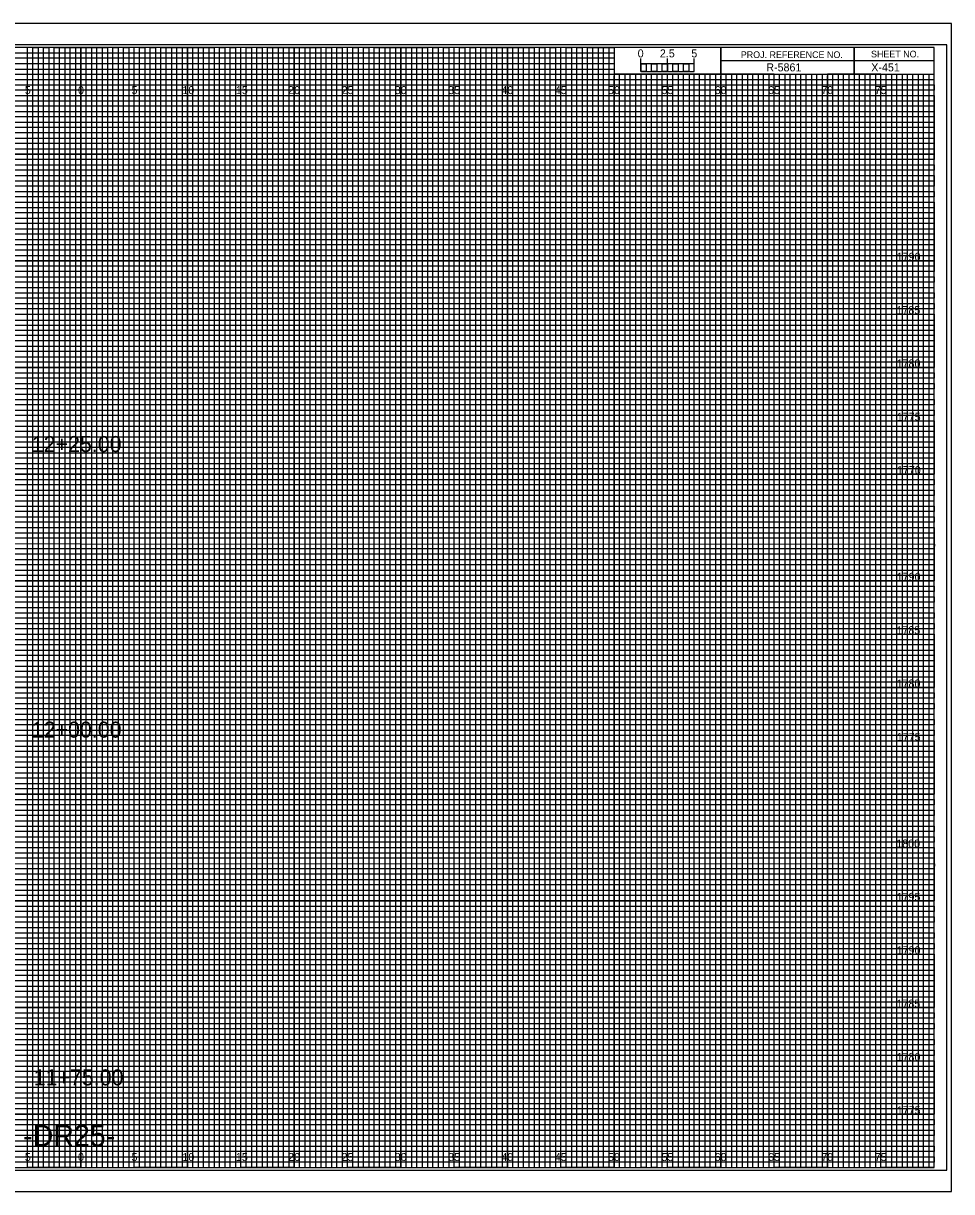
# Model space of a CAD drawing. Extents: x -7 to 162, y -2 to 327.
# Drawn here: x 74.6 to 161.7, y 217.7 to 327.2 of the extents above; entities that cross this region are included whole.
import ezdxf

# ---------------------------------------------------------------- set-up
doc = ezdxf.new("R2010")
doc.units = 0
for name, color, linetype in [('Prop Horizontal Alignment', 7, 'Continuous'), ('Prop XS Alignment Label', 7, 'Continuous'), ('Prop XS Bar Scale Labels', 7, 'Continuous'), ('Prop XS Project Number', 7, 'Continuous'), ('Prop XS Sheet Number', 7, 'Continuous'), ('Raster_Level_0', 7, 'Continuous'), ('Scratch_Level_3', 7, 'Continuous'), ('Sheet Cross Section CELL', 7, 'Continuous'), ('Sheet Cross Section Grid Major CELL', 7, 'Continuous'), ('Sheet Cross Section Grid Middle CELL', 7, 'Continuous'), ('Sheet Cross Section Grid Minor 1 CELL', 7, 'Continuous'), ('Sheet Cross Section Grid Minor 2 CELL', 7, 'Continuous'), ('Sheet Cross Section Scale CELL', 7, 'Continuous'), ('Sheet Cutting Line CELL', 7, 'Continuous'), ('Sheet DOT Grid CELL', 7, 'Continuous'), ('Sheet Plot Border Inside CELL', 7, 'Continuous'), ('Sheet Plot Border Outside CELL', 7, 'Continuous')]:
    doc.layers.add(name, color=color, linetype=linetype)

msp = doc.modelspace()

# ---------------------------------------------------------------- linework, layer by layer
at = {"layer": 'Sheet Cross Section CELL'}
for p, q in [((152.5, 325), (152.5, 322.5)), ((152.5, 322.5), (152.5, 325)), ((160, 323.75), (140, 323.75)), ((140, 323.75), (140, 322.5)), ((140, 322.5), (160, 322.5))]:
    msp.add_line(p, q, dxfattribs=at)
for points in [[(160, 325), (0, 325), (0, 220), (160, 220)], [(140, 325), (130, 325), (130, 322.51), (140, 322.51)], [(160, 325), (140, 325), (140, 322.5), (160, 322.5)]]:
    msp.add_lwpolyline(points, close=True, dxfattribs=at)
at = {"layer": 'Sheet Cross Section Grid Major CELL'}
for p, q in [((75, 325), (70, 325)), ((75, 220), (75, 325)), ((85, 325), (80, 325)), ((80, 325), (80, 220)), ((85, 220), (85, 325)), ((95, 325), (90, 325)), ((90, 325), (90, 220)), ((95, 220), (95, 325)), ((105, 325), (100, 325)), ((100, 325), (100, 220)), ((105, 220), (105, 325)), ((115, 325), (110, 325)), ((110, 325), (110, 220)), ((115, 220), (115, 325)), ((125, 325), (120, 325)), ((120, 325), (120, 220)), ((125, 220), (125, 325)), ((130, 325), (130, 220)), ((135, 220), (135, 322.5)), ((145, 322.5), (140, 322.5)), ((140, 322.5), (140, 220)), ((145, 220), (145, 322.5)), ((155, 322.5), (150, 322.5)), ((150, 322.5), (150, 220)), ((155, 220), (155, 322.5)), ((80, 220), (75, 220)), ((90, 220), (85, 220)), ((100, 220), (95, 220)), ((110, 220), (105, 220)), ((120, 220), (115, 220)), ((130, 220), (125, 220)), ((140, 220), (135, 220)), ((150, 220), (145, 220)), ((160, 220), (155, 220)), ((160, 220), (160, 220))]:
    msp.add_line(p, q, dxfattribs=at)
for points in [[(0, 320), (160, 320), (160, 315), (0, 315)], [(0, 310), (160, 310), (160, 305), (0, 305)], [(0, 300), (160, 300), (160, 295), (0, 295)], [(0, 290), (160, 290), (160, 285), (0, 285)], [(0, 280), (160, 280), (160, 275), (0, 275)], [(0, 270), (160, 270), (160, 265), (0, 265)], [(0, 260), (160, 260), (160, 255), (0, 255)], [(0, 250), (160, 250), (160, 245), (0, 245)], [(0, 240), (160, 240), (160, 235), (0, 235)], [(0, 230), (160, 230), (160, 225), (0, 225)]]:
    msp.add_lwpolyline(points, dxfattribs=at)
at = {"layer": 'Sheet Cross Section Grid Middle CELL'}
for points in [[(72.5, 220), (77.5, 220), (77.5, 325), (82.5, 325), (82.5, 220), (87.5, 220), (87.5, 325), (92.5, 325), (92.5, 220), (97.5, 220), (97.5, 325), (102.5, 325), (102.5, 220), (107.5, 220), (107.5, 325), (112.5, 325), (112.5, 220), (117.5, 220), (117.5, 325), (122.5, 325), (122.5, 220), (127.5, 220), (127.5, 325), (129.97, 325), (130, 325), (130, 322.5), (132.5, 322.5), (132.5, 220), (137.5, 220), (137.5, 322.5), (142.5, 322.5), (142.5, 220), (147.5, 220), (147.5, 322.5), (152.5, 322.5), (152.5, 220), (157.5, 220), (157.5, 322.5)], [(0, 322.5), (137.5, 322.5)], [(0, 312.5), (160, 312.5), (160, 317.5), (0, 317.5)], [(0, 302.5), (160, 302.5), (160, 307.5), (0, 307.5)], [(0, 292.5), (160, 292.5), (160, 297.5), (0, 297.5)], [(0, 282.5), (160, 282.5), (160, 287.5), (0, 287.5)], [(0, 272.5), (160, 272.5), (160, 277.5), (0, 277.5)], [(0, 262.5), (160, 262.5), (160, 267.5), (0, 267.5)], [(0, 252.5), (160, 252.5), (160, 257.5), (0, 257.5)], [(0, 242.5), (160, 242.5), (160, 247.5), (0, 247.5)], [(0, 232.5), (160, 232.5), (160, 237.5), (0, 237.5)], [(0, 222.5), (160, 222.5), (160, 227.5), (0, 227.5)]]:
    msp.add_lwpolyline(points, dxfattribs=at)
at = {"layer": 'Sheet Cross Section Grid Minor 1 CELL'}
for p, q in [((0, 324.5), (130, 324.5)), ((130, 324.5), (130, 323.99)), ((130, 323.99), (0, 323.99)), ((0, 323.5), (130, 323.5)), ((130, 323.5), (130, 322.94)), ((130, 322.94), (0, 322.94)), ((0, 322), (160, 322))]:
    msp.add_line(p, q, dxfattribs=at)
for points in [[(0, 321.5), (135, 321.5), (160, 321.5), (160, 321), (0, 321)], [(0, 320.5), (160, 320.5), (160, 319.5), (0, 319.5)], [(0, 319), (160, 319), (160, 318.5), (0, 318.49)], [(0, 318), (160, 318), (160, 317), (0, 317)], [(0, 316.5), (160, 316.5), (160, 316), (0, 316)], [(0, 315.5), (160, 315.5), (160, 314.5), (0, 314.5)], [(0, 314), (160, 314), (160, 313.5), (0, 313.5)], [(0, 313), (160, 313), (160, 312), (0, 312)], [(0, 311.5), (160, 311.5), (160, 311), (0, 311)], [(0, 310.5), (160, 310.5), (160, 309.5), (0, 309.5)], [(0, 309), (160, 309), (160, 308.5), (0, 308.5)], [(0, 308), (160, 308), (160, 306.98), (160, 306.5), (160, 306), (0, 306)], [(0, 307), (160, 307), (160, 306.5), (0, 306.5)], [(0, 305.5), (160, 305.5), (160, 304.5), (0, 304.51)], [(0, 304.51), (160, 304.5), (160, 304), (0, 304)], [(0, 303.5), (160, 303.5), (160, 303), (0, 303)], [(0, 302), (160, 302), (160, 301.5), (0, 301.5)], [(0, 301), (160, 301), (160, 300.5), (0, 300.5)], [(-0.04, 299.44), (160, 299.44), (160, 298.94), (-0.04, 298.94)], [(0, 298.5), (160, 298.5), (160, 298), (0, 298)], [(0, 297), (160, 297), (160, 296.5), (0, 296.5)], [(0, 296), (160, 296), (160, 295.5), (0, 295.5)], [(0, 294.5), (160, 294.5), (160, 294), (0, 294)], [(0, 293.5), (160, 293.5), (160, 293), (0, 293)], [(0, 292), (160, 292), (160, 291.5), (0, 291.5)], [(0, 291), (160, 291), (160, 290.5), (0, 290.5)], [(0, 289.5), (160, 289.5), (160, 288.99), (0, 289)], [(0, 288.5), (160, 288.5), (160, 288), (0, 288)], [(0, 287), (160, 287), (160, 286.5), (0, 286.5)], [(0, 286), (160, 286), (160, 285.5), (0, 285.5)], [(0, 284.5), (160, 284.5), (160, 284), (0, 284)], [(0, 283.5), (160, 283.5), (160, 283), (0, 283)], [(0, 282), (160, 282), (160, 281.5), (0, 281.5)], [(0, 281), (160, 281), (160, 280.5), (0, 280.5)], [(0, 279.5), (160, 279.5), (160, 279), (0, 279)], [(0, 278.5), (160.03, 278.45), (160, 278), (0, 278)], [(0, 277), (160, 277), (160, 276.5), (0, 276.5)], [(0, 276), (160, 276), (160, 275.5), (0, 275.5)], [(0, 274.5), (160, 274.5), (160, 274), (0, 274)], [(0, 273.5), (160, 273.5), (160, 273), (0, 273)], [(0, 272), (160, 272), (160, 271.5), (0, 271.5)], [(0, 271), (160, 271), (160, 270.5), (0, 270.5)], [(0, 269.5), (160, 269.5), (160, 269), (0, 269)], [(0, 268.5), (160, 268.5), (160, 268), (0, 268)], [(0, 267), (160, 267), (160, 266.5), (0, 266.5)], [(0, 266), (160, 266), (160, 265.5), (0, 265.5)], [(0, 264.5), (160, 264.5), (160, 264), (0, 264)], [(0, 263.5), (160, 263.5), (160, 263), (0, 263)], [(0, 262), (160, 262), (160, 261.5), (0, 261.5)], [(0, 261), (160, 261), (160, 260.5), (0, 260.5)], [(0, 259.5), (160, 259.5), (160, 258.99), (0, 259)], [(0, 258.5), (160, 258.5), (160, 258), (0, 258)], [(0, 257), (160, 257), (160, 256.5), (0, 256.5)], [(0, 256), (160, 256), (160, 255.5), (0, 255.5)], [(0, 254.5), (160, 254.5), (160, 254), (0, 254)], [(0, 253.5), (160, 253.5), (160, 253), (0, 253)], [(0, 252), (160, 252), (160, 251.5), (0, 251.5)], [(0, 251), (160, 251), (160, 250.5), (0, 250.5)], [(0, 249.5), (160, 249.5), (160, 249), (0, 249)], [(0, 248.5), (160.03, 248.46), (160, 248), (0, 248)], [(0, 247), (160, 247), (160, 246.5), (0, 246.5)], [(0, 246), (160, 246), (160, 245.5), (0, 245.5)], [(0, 244.5), (160, 244.5), (160, 244), (0, 244)], [(0, 243.5), (160, 243.5), (160, 243), (0, 243)], [(0, 242), (160, 242), (160, 241.5), (0, 241.5)], [(0, 241), (160, 241), (160, 240.5), (0, 240.5)], [(0, 239.5), (160, 239.5), (160, 239), (0, 239)], [(0, 238.5), (160, 238.5), (160, 238), (0, 238)], [(0, 237), (160, 237), (160, 236.5), (0, 236.5)], [(0, 236), (160, 236), (160, 235.5), (0, 235.5)], [(0, 234.5), (160, 234.5), (160, 234), (0, 234)], [(0, 233.5), (160, 233.5), (160, 233), (0, 233)], [(0, 232), (160, 232), (160, 231.5), (0, 231.5)], [(0, 231), (160, 231), (160, 230.5), (0, 230.5)], [(0, 229.5), (160, 229.5), (160, 229), (0, 229)], [(0, 228.5), (160, 228.5), (160, 228), (0, 228)], [(0, 227), (160, 227), (160, 226.5), (0, 226.5)], [(0, 226), (160, 226), (160, 225.5), (0, 225.5)], [(0, 224.5), (160, 224.5), (160, 224), (0, 224)], [(0, 223.5), (160, 223.5), (160, 223), (0, 223)], [(0, 222), (160, 222), (160, 221.5), (0, 221.5)], [(0, 221), (160, 221), (160, 220.5), (0, 220.5)]]:
    msp.add_lwpolyline(points, dxfattribs=at)
at = {"layer": 'Sheet Cross Section Grid Minor 2 CELL'}
for p, q in [((133.5, 322.5), (133, 322.5)), ((133, 322.5), (133, 220)), ((133.5, 220), (133.5, 322.5)), ((134.5, 322.5), (134, 322.5)), ((134, 322.5), (134, 220)), ((134.5, 220), (134.5, 322.5)), ((133, 220), (132.5, 220)), ((134, 220), (133.5, 220))]:
    msp.add_line(p, q, dxfattribs=at)
for points in [[(75, 220), (75.5, 220), (75.5, 325), (76, 325), (76, 220)], [(76, 220), (76.5, 220), (76.5, 325), (77, 325), (77, 220)], [(77.5, 220), (78, 220), (78, 325), (78.5, 325), (78.5, 220)], [(78.5, 220), (79, 220), (79, 325), (79.5, 325), (79.5, 220)], [(80, 220), (80.5, 220), (80.5, 325), (81, 325), (81, 220)], [(81, 220), (81.5, 220), (81.5, 325), (82, 325), (82, 220)], [(82.5, 220), (83, 220), (83, 325), (83.5, 325), (83.5, 220)], [(83.5, 220), (84, 220), (84, 325), (84.5, 325), (84.5, 220)], [(85, 220), (85.5, 220), (85.5, 325), (86, 325), (86, 220)], [(86, 220), (86.5, 220), (86.5, 325), (87, 325), (87, 220)], [(87.5, 220), (88, 220), (88, 325), (88.5, 325), (88.5, 220)], [(88.5, 220), (89, 220), (89, 325), (89.5, 325), (89.5, 220)], [(90, 220), (90.5, 220), (90.5, 325), (91, 325), (91, 220)], [(91, 220), (91.5, 220), (91.5, 325), (92, 325), (92, 220)], [(92.5, 220), (93, 220), (93, 325), (93.5, 325), (93.5, 220)], [(93.5, 220), (94, 220), (94, 325), (94.5, 325), (94.5, 220)], [(95, 220), (95.5, 220), (95.5, 325), (96, 325), (96, 220)], [(96, 220), (96.5, 220), (96.5, 325), (97, 325), (97, 220)], [(97.5, 220), (98, 220), (98, 325), (98.5, 325), (98.5, 220)], [(98.5, 220), (99, 220), (99, 325), (99.5, 325), (99.5, 220)], [(100, 220), (100.5, 220), (100.5, 325), (101, 325), (101, 220)], [(101, 220), (101.5, 220), (101.5, 325), (102, 325), (102, 220)], [(102.5, 220), (103, 220), (103, 325), (103.5, 325), (103.5, 220)], [(103.5, 220), (104, 220), (104, 325), (104.5, 325), (104.5, 220)], [(105, 220), (105.5, 220), (105.5, 325), (106, 325), (106, 220)], [(106, 220), (106.5, 220), (106.5, 325), (107, 325), (107, 220)], [(107.5, 220), (108, 220), (108, 325), (108.5, 325), (108.5, 220)], [(108.5, 220), (109, 220), (109, 325), (109.5, 325), (109.5, 220)], [(110, 220), (110.5, 220), (110.5, 325), (111, 325), (111, 220)], [(111, 220), (111.5, 220), (111.5, 325), (112, 325), (112, 220)], [(112.5, 220), (113, 220), (113, 325), (113.5, 325), (113.5, 220)], [(113.5, 220), (114, 220), (114, 325), (114.5, 325), (114.5, 220)], [(115, 220), (115.5, 220), (115.5, 325), (116, 325), (116, 220)], [(116, 220), (116.5, 220), (116.5, 325), (117, 325), (117, 220)], [(117.5, 220), (118, 220), (118, 325), (118.5, 325), (118.5, 220)], [(118.5, 220), (119, 220), (119, 325), (119.5, 325), (119.5, 220)], [(120, 220), (120.5, 220), (120.5, 325), (121, 325), (121, 220)], [(121, 220), (121.5, 220), (121.5, 325), (122, 325), (122, 220)], [(122.5, 220), (123, 220), (123, 325), (123.5, 325), (123.5, 220)], [(123.5, 220), (124, 220), (124, 325), (124.5, 325), (124.5, 220)], [(125, 220), (125.5, 220), (125.5, 325), (126, 325), (126, 220)], [(126, 220), (126.5, 220), (126.5, 325), (127, 325), (127, 220)], [(127.5, 220), (128, 220), (128, 325), (128.5, 325), (128.5, 220)], [(128.5, 220), (129, 220), (129, 325), (129.5, 325), (129.5, 220)], [(130, 220), (130.5, 220), (130.5, 322.5), (131.01, 322.5), (131.01, 220)], [(131, 220), (131.5, 220), (131.5, 322.5), (132, 322.5), (132, 220)], [(135, 220), (135.49, 220), (135.49, 322.5), (136, 322.5), (136, 220)], [(136, 220), (136.5, 220), (136.5, 322.5), (137.03, 322.5), (137.03, 220)], [(137.5, 220), (138, 220), (138, 322.5), (138.5, 322.5), (138.5, 220)], [(138.5, 220), (139, 220), (139, 322.5), (139.5, 322.5), (139.5, 220)], [(140, 220), (140.5, 220), (140.5, 322.5), (141, 322.5), (141, 220)], [(141, 220), (141.5, 220), (141.5, 322.5), (142, 322.5), (142, 220)], [(142.5, 220), (143, 220), (143, 322.5), (143.5, 322.5), (143.5, 220)], [(143.5, 220), (144, 220), (144, 322.5), (144.5, 322.5), (144.5, 220)], [(145, 220), (145.5, 220), (145.5, 322.5), (146, 322.5), (146, 220)], [(146, 220), (146.5, 220), (146.5, 322.5), (147, 322.5), (147, 220)], [(147.5, 220), (148, 220), (148, 322.5), (148.5, 322.5), (148.5, 220)], [(148.5, 220), (149, 220), (149, 322.5), (149.5, 322.5), (149.5, 220)], [(150, 220), (150.5, 220), (150.5, 322.5), (151, 322.5), (151, 220)], [(151, 220), (151.5, 220), (151.5, 322.5), (152, 322.5), (152, 220)], [(152.5, 220), (153, 220), (153, 322.5), (153.5, 322.5), (153.5, 220)], [(153.5, 220), (154, 220), (154, 322.5), (154.5, 322.5), (154.5, 220)], [(155, 220), (155.5, 220), (155.5, 322.5), (156, 322.5), (156, 220)], [(156, 220), (156.5, 220), (156.5, 322.5), (157, 322.5), (157, 220)], [(157.5, 220), (158, 220), (158, 322.5), (158.5, 322.5), (158.5, 220)], [(158.5, 220), (159, 220), (159, 322.5), (159.5, 322.5), (159.5, 220)]]:
    msp.add_lwpolyline(points, dxfattribs=at)
at = {"layer": 'Sheet Cross Section Scale CELL'}
for p, q in [((132.5, 322.75), (132.5, 323.95)), ((132.5, 323.45), (132.5, 323.95)), ((135, 322.75), (135, 323.95)), ((137.5, 322.75), (137.5, 323.95)), ((137.5, 323.45), (137.5, 323.95))]:
    msp.add_line(p, q, dxfattribs=at)
for points in [[(137.5, 323.45), (132.5, 323.45), (132.5, 322.75), (137.5, 322.75)], [(132.5, 323.45), (133, 323.45), (133, 322.75), (132.5, 322.75)], [(133.5, 323.45), (134, 323.45), (134, 322.75), (133.5, 322.75)], [(134.5, 323.45), (135, 323.45), (135, 322.75), (134.5, 322.75)], [(135.5, 323.45), (136, 323.45), (136, 322.75), (135.5, 322.75)], [(136.5, 323.45), (137, 323.45), (137, 322.75), (136.5, 322.75)]]:
    msp.add_lwpolyline(points, close=True, dxfattribs=at)
at = {"layer": 'Sheet Cutting Line CELL'}
for p, q in [((161.65, 327.25), (-6.7, 327.25)), ((-6.7, 217.75), (161.65, 217.75))]:
    msp.add_line(p, q, dxfattribs=at)
at = {"layer": 'Sheet DOT Grid CELL'}
for p, q in [((75, 220), (75, 325)), ((80, 220), (80, 325)), ((85, 220), (85, 325)), ((90, 220), (90, 325)), ((95, 220), (95, 325)), ((100, 220), (100, 325)), ((105, 220), (105, 325)), ((110, 220), (110, 325)), ((115, 220), (115, 325)), ((120, 220), (120, 325)), ((125, 220), (125, 325)), ((130, 220), (130, 322.34)), ((135, 220), (135, 322.34)), ((140, 220), (140, 322.34)), ((145, 220), (145, 322.34)), ((150, 220), (150, 322.34)), ((155, 220), (155, 322.34)), ((0, 320), (160, 320)), ((0, 315), (160, 315)), ((0, 310), (160, 310)), ((0, 305), (160, 305)), ((0, 300), (160, 300)), ((0, 295), (160, 295)), ((0, 290), (160, 290)), ((0, 285), (160, 285)), ((0, 280), (160, 280)), ((0, 275), (160, 275)), ((0, 270), (160, 270)), ((0, 265), (160, 265)), ((0, 260), (160, 260)), ((0, 255), (160, 255)), ((0, 250), (160, 250)), ((0, 245), (160, 245)), ((0, 240), (160, 240)), ((0, 235), (160, 235)), ((0, 230), (160, 230)), ((0, 225), (160, 225))]:
    msp.add_line(p, q, dxfattribs=at)
at = {"layer": 'Sheet Plot Border Inside CELL'}
msp.add_lwpolyline([(-5.4, 219.75), (161.2, 219.75), (161.2, 325.25), (-5.4, 325.25)], close=True, dxfattribs=at)
at = {"layer": 'Sheet Plot Border Outside CELL'}
msp.add_lwpolyline([(-6.7, 217.75), (161.65, 217.75), (161.65, 327.25), (-6.7, 327.25)], close=True, dxfattribs=at)

# ---------------------------------------------------------------- texts
at = {"layer": 'Prop Horizontal Alignment'}
for s, p in [('12+25.00', (75.39, 287.07)), ('12+00.00', (75.39, 260.3)), ('11+75.00', (75.57, 227.71))]:
    msp.add_text(s, height=1.5, dxfattribs=at).set_placement(p)
at = {"layer": 'Prop XS Alignment Label'}
msp.add_text('-DR25-', height=2, dxfattribs=at).set_placement((74.59, 222))
at = {"layer": 'Prop XS Bar Scale Labels'}
for s, p in [('2.5', (134.29, 324.06)), ('5', (137.24, 324.06))]:
    msp.add_text(s, height=0.75, dxfattribs=at).set_placement(p)
at = {"layer": 'Prop XS Project Number'}
msp.add_text('R-5861', height=0.75, dxfattribs=at).set_placement((144.27, 322.75))
at = {"layer": 'Prop XS Sheet Number'}
msp.add_text('X-451', height=0.75, dxfattribs=at).set_placement((154.11, 322.75))
at = {"layer": 'Raster_Level_0'}
for s, p in [('5', (74.74, 320.62)), ('0', (79.73, 320.62)), ('0', (79.73, 320.62)), ('5', (84.74, 320.62)), ('10', (89.52, 320.62)), ('15', (94.53, 320.62)), ('20', (99.43, 320.62)), ('25', (104.44, 320.62)), ('30', (109.43, 320.62)), ('35', (114.44, 320.62)), ('40', (119.43, 320.62)), ('45', (124.44, 320.62)), ('50', (129.43, 320.62)), ('55', (134.44, 320.62)), ('60', (139.43, 320.62)), ('65', (144.44, 320.62)), ('70', (149.43, 320.62)), ('75', (154.44, 320.62)), ('5', (74.74, 220.62)), ('0', (79.73, 220.62)), ('0', (79.73, 220.62)), ('5', (84.74, 220.62)), ('10', (89.52, 220.62)), ('15', (94.53, 220.62)), ('20', (99.43, 220.62)), ('25', (104.44, 220.62)), ('30', (109.43, 220.62)), ('35', (114.44, 220.62)), ('40', (119.43, 220.62)), ('45', (124.44, 220.62)), ('50', (129.43, 220.62)), ('55', (134.44, 220.62)), ('60', (139.43, 220.62)), ('65', (144.44, 220.62)), ('70', (149.43, 220.62)), ('75', (154.44, 220.62))]:
    msp.add_text(s, height=0.75, dxfattribs=at).set_placement(p)
at = {"layer": 'Scratch_Level_3'}
for s, p in [('1790', (156.5, 305)), ('1785', (156.48, 300)), ('1780', (156.49, 295)), ('1775', (156.51, 290)), ('1770', (156.52, 285)), ('1790', (156.5, 275)), ('1785', (156.48, 270)), ('1780', (156.49, 265)), ('1775', (156.51, 260)), ('1800', (156.46, 250)), ('1795', (156.49, 245)), ('1790', (156.5, 240)), ('1785', (156.48, 235)), ('1780', (156.49, 230)), ('1775', (156.51, 225))]:
    msp.add_text(s, height=0.75, dxfattribs=at).set_placement(p)
at = {"layer": 'Sheet Cross Section CELL'}
for s, p in [('PROJ. REFERENCE NO.', (141.88, 324)), ('SHEET NO.', (154.09, 324.06))]:
    msp.add_text(s, height=0.625, dxfattribs=at).set_placement(p)
at = {"layer": 'Sheet Cross Section Scale CELL'}
msp.add_text('0', height=0.75, dxfattribs=at).set_placement((132.21, 324.06))

doc.saveas('drawing.dxf')
